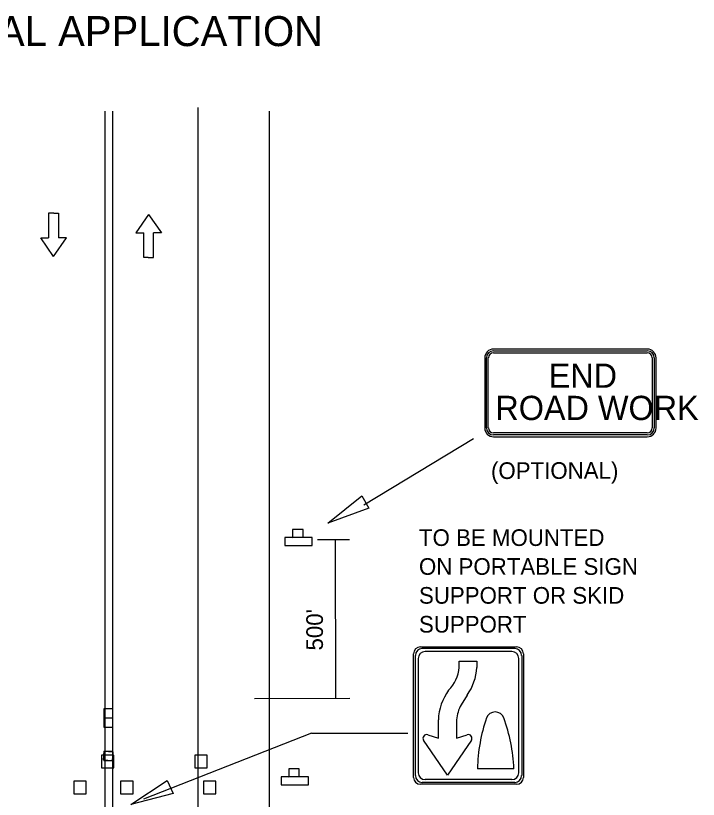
# Model space of a CAD drawing. Extents: x 1531.38 to 1538.58, y 1529.59 to 1539.28.
# Drawn here: x 1535.582 to 1538.043, y 1536.457 to 1539.279 of the extents above; entities that cross this region are included whole.
import ezdxf

# ---------------------------------------------------------------- set-up
doc = ezdxf.new("R2010")
doc.units = 0
for name, color, linetype in [('DETL-DIMS', 7, 'Continuous'), ('DETL-LINE', 7, 'Continuous'), ('DETL-NOTE', 7, 'Continuous'), ('DETL-TITL', 7, 'Continuous'), ('USER-BORD', 7, 'Continuous')]:
    doc.layers.add(name, color=color, linetype=linetype)

# ---------------------------------------------------------------- blocks, each defined once
blk = doc.blocks.new('TD')
at = {"layer": 'USER-BORD'}
for p, q in [((0, 0), (-0.0539, -0.077)), ((0, 0), (0.0539, -0.077)), ((-0.0539, -0.077), (-0.0208, -0.077)), ((-0.0208, -0.1803), (-0.0208, -0.077)), ((0.0208, -0.1803), (0.0208, -0.077)), ((0.0539, -0.077), (0.0208, -0.077)), ((-0.0017, -0.1803), (-0.0208, -0.1803)), ((-0.0017, -0.1803), (0.0017, -0.1803)), ((0.0017, -0.1803), (0.0208, -0.1803))]:
    blk.add_line(p, q, dxfattribs=at)
blk = doc.blocks.new('CD20')
at = {"layer": 'USER-BORD'}
blk.add_lwpolyline([(-0.0625, -0.0625), (0, -0.0625), (0, 0), (-0.0625, 0)], close=True, dxfattribs=at)
blk = doc.blocks.new('SIGN13')
at = {"layer": 'USER-BORD'}
for points in [[(-0.0134, 0.0182), (0.011, 0.0189), (0.011, 0.0371), (-0.0134, 0.0371)], [(-0.0314, 0.0182), (-0.0314, 0), (0.032, 0), (0.032, 0.0182)]]:
    blk.add_lwpolyline(points, close=True, dxfattribs=at)

msp = doc.modelspace()

# ---------------------------------------------------------------- linework, layer by layer
at = {"layer": 'DETL-DIMS'}
for p, q in [((1536.8375, 1537.517), (1537.2322, 1537.7558)), ((1536.6709, 1537.3927), (1536.7851, 1537.3928)), ((1536.7365, 1536.8203), (1536.7354, 1537.3927)), ((1536.4435, 1536.8196), (1536.7863, 1536.8205)), ((1536.6491, 1536.6947), (1536.0433, 1536.4571)), ((1536.6491, 1536.6947), (1536.9963, 1536.6945))]:
    msp.add_line(p, q, dxfattribs=at)
for points in [[(1536.8299, 1537.5499), (1536.8553, 1537.5049), (1536.7075, 1537.4515)], [(1536.1288, 1536.525), (1536.1499, 1536.478), (1535.9979, 1536.4382)]]:
    msp.add_lwpolyline(points, close=True, dxfattribs=at)
at = {"layer": 'DETL-LINE'}
for p, q in [((1536.2393, 1538.948), (1536.2393, 1535.6775)), ((1535.9039, 1538.9346), (1535.9039, 1531.7918)), ((1535.9309, 1538.9346), (1535.9309, 1531.7918)), ((1536.4962, 1538.9346), (1536.4962, 1531.7918)), ((1537.8591, 1538.0778), (1537.3044, 1538.0778)), ((1537.3044, 1538.0714), (1537.8591, 1538.0714)), ((1537.3044, 1538.0647), (1537.8591, 1538.0647)), ((1537.2731, 1538.0465), (1537.2731, 1537.7942)), ((1537.2795, 1537.7942), (1537.2795, 1538.0465)), ((1537.2861, 1537.7942), (1537.2861, 1538.0465)), ((1537.8771, 1538.0465), (1537.8771, 1537.7942)), ((1537.8772, 1538.0463), (1537.8771, 1538.0465)), ((1537.8844, 1538.0465), (1537.8844, 1537.7942)), ((1537.8908, 1537.7942), (1537.8908, 1538.0465)), ((1537.8591, 1537.7762), (1537.3044, 1537.7762)), ((1537.8591, 1537.769), (1537.3044, 1537.769)), ((1537.3044, 1537.7626), (1537.8591, 1537.7626)), ((1537.0416, 1537.0055), (1537.3877, 1537.0055)), ((1537.3816, 1536.9994), (1537.0479, 1536.9994)), ((1537.0169, 1536.5358), (1537.0169, 1536.9808)), ((1537.0231, 1536.5419), (1537.0231, 1536.9747)), ((1537.0333, 1536.9643), (1537.0333, 1536.5523)), ((1537.3712, 1536.989), (1537.0581, 1536.989)), ((1537.3959, 1536.5523), (1537.3959, 1536.9643)), ((1537.4063, 1536.9747), (1537.4063, 1536.5419)), ((1537.4124, 1536.9808), (1537.4124, 1536.5358)), ((1537.1813, 1536.9543), (1537.2446, 1536.9543)), ((1537.1813, 1536.9319), (1537.1813, 1536.9543)), ((1537.2446, 1536.9543), (1537.2446, 1536.9319)), ((1537.2102, 1536.832), (1537.1879, 1536.7974)), ((1537.1059, 1536.6767), (1537.1059, 1536.7427)), ((1537.1718, 1536.7427), (1537.1718, 1536.6767)), ((1537.0676, 1536.6891), (1537.106, 1536.6766)), ((1537.1718, 1536.6766), (1537.2102, 1536.6891)), ((1537.1388, 1536.5431), (1537.0528, 1536.6695)), ((1537.2249, 1536.6695), (1537.1388, 1536.5431)), ((1537.3786, 1536.5668), (1537.2468, 1536.5668)), ((1537.3877, 1536.5111), (1537.0416, 1536.5111)), ((1537.3816, 1536.5172), (1537.0479, 1536.5172)), ((1537.3712, 1536.5276), (1537.0581, 1536.5276))]:
    msp.add_line(p, q, dxfattribs=at)
for points in [[(1535.892, 1536.5705), (1535.9368, 1536.5705), (1535.9368, 1536.6153), (1535.892, 1536.6153)], [(1536.2278, 1536.5705), (1536.2726, 1536.5705), (1536.2726, 1536.6153), (1536.2278, 1536.6153)], [(1535.7917, 1536.4767), (1535.8365, 1536.4767), (1535.8365, 1536.5215), (1535.7917, 1536.5215)], [(1535.9606, 1536.4767), (1536.0054, 1536.4767), (1536.0054, 1536.5215), (1535.9606, 1536.5215)], [(1536.259, 1536.4767), (1536.3038, 1536.4767), (1536.3038, 1536.5215), (1536.259, 1536.5215)]]:
    msp.add_lwpolyline(points, close=True, dxfattribs=at)
for centre, radius, start, end in [((1537.3045, 1538.0462), 0.0316, 90, 180), ((1537.3045, 1538.0462), 0.0252, 90, 180), ((1537.3045, 1538.0462), 0.0181, 90, 180), ((1537.8591, 1538.0462), 0.0316, 0, 90), ((1537.8591, 1538.0462), 0.0252, 0, 90), ((1537.8591, 1538.0462), 0.0181, 0, 90), ((1537.3045, 1537.7941), 0.0316, 180, 270), ((1537.3045, 1537.7941), 0.0252, 180, 270), ((1537.3045, 1537.7941), 0.0181, 180, 270), ((1537.8591, 1537.7941), 0.0316, 270, 0), ((1537.8591, 1537.7941), 0.0181, 270, 0), ((1537.8591, 1537.7941), 0.0252, 270, 0), ((1537.0416, 1536.9808), 0.0247, 90, 180), ((1537.0478, 1536.9746), 0.0247, 90, 180), ((1537.3815, 1536.9746), 0.0247, 360, 90), ((1537.3877, 1536.9808), 0.0247, 360, 90), ((1537.0581, 1536.9643), 0.0247, 90, 180), ((1537.3712, 1536.9643), 0.0247, 360, 90), ((1537.0489, 1536.9433), 0.1329, 315.1307, 355.032), ((1537.0489, 1536.9433), 0.196, 325.3872, 356.6343), ((1537.3034, 1536.7339), 0.1977, 144.1907, 177.4446), ((1537.3034, 1536.7339), 0.1319, 151.1838, 176.1678), ((1537.3106, 1536.7383), 0.033, 20.3641, 159.6359), ((1537.8504, 1536.5525), 0.6039, 160.9328, 178.6381), ((1536.7764, 1536.54), 0.6028, 2.5529, 20.3658), ((1537.0635, 1536.6767), 0.0129, 72, 214.2603), ((1537.2142, 1536.6767), 0.0129, 325.7397, 108), ((1537.0478, 1536.542), 0.0247, 180, 270), ((1537.0581, 1536.5523), 0.0247, 180, 270), ((1537.3712, 1536.5523), 0.0247, 270, 360), ((1537.3815, 1536.542), 0.0247, 270, 360), ((1537.0416, 1536.5358), 0.0247, 180, 270), ((1537.3877, 1536.5358), 0.0247, 270, 360)]:
    msp.add_arc(centre, radius, start, end, dxfattribs=at)

# ---------------------------------------------------------------- block references
for name, p, xscale, yscale, rotation in [('TD', (1535.719, 1538.4118), 0.8611764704, 0.8611764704, 180), ('CD20', (1535.901, 1536.6296), 0.5153677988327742, -0.5153677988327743, 175.8377313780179)]:
    msp.add_blockref(name, p, dxfattribs=dict(at, xscale=xscale, yscale=yscale, rotation=rotation))
for name, p, xscale, yscale in [('TD', (1536.0618, 1538.5629), 0.8611764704, 0.8611764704), ('SIGN13', (1536.6011, 1537.3711), 1.550372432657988, 1.550372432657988), ('CD20', (1535.9329, 1536.7827), 0.5153677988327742, 0.5153677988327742), ('CD20', (1535.9329, 1536.7485), 0.5153677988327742, 0.5153677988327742), ('CD20', (1535.9329, 1536.6285), 0.5153677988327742, 0.5153677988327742), ('SIGN13', (1536.5878, 1536.5091), 1.550372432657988, 1.550372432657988)]:
    msp.add_blockref(name, p, dxfattribs=dict(at, xscale=xscale, yscale=yscale))

# ---------------------------------------------------------------- texts
for s, p in [('END', (1537.5034, 1537.9385)), ('ROAD WORK', (1537.3114, 1537.8225))]:
    msp.add_text(s, height=0.08731, rotation=360, dxfattribs=at).set_placement(p)
at = {"layer": 'DETL-NOTE'}
for s, rotation, p in [('(OPTIONAL)', 0.1133, (1537.2957, 1537.6102)), ("500'", 90, (1536.69, 1536.9925))]:
    msp.add_text(s, height=0.06, rotation=rotation, dxfattribs=at).set_placement(p)
for s, p in [('TO BE MOUNTED', (1537.0361, 1537.3691)), ('ON PORTABLE SIGN', (1537.0361, 1537.2651)), ('SUPPORT OR SKID', (1537.0361, 1537.1611)), ('SUPPORT', (1537.0361, 1537.0571))]:
    msp.add_text(s, height=0.06, dxfattribs=at).set_placement(p)
at = {"layer": 'DETL-TITL'}
msp.add_text('TEMPORARY TRAFFIC CONTROL TYPICAL APPLICATION', height=0.108, dxfattribs=at).set_placement((1532.7424, 1539.169))

doc.saveas('drawing.dxf')
